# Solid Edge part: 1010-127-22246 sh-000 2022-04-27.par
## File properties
Author: lukasz.lemanski
Template: iso metric part.par
Last saved by: lukasz.lemanski
Revision: 1
Application: Solid Edge
Username: lukasz.lemanski
Gęstość: 0,000 kg/m^3
Dokładność: 0,990
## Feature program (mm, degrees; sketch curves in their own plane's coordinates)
body "unnamed Body 1"
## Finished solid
Body 1: solid body, 3347 faces, 8657 edges, 5599 vertices, 4 separate solids.
  Faces by surface: plane 2607, cylinder 338, spline 240, cone 78, torus 33, sphere 30, spun 21
  Edges by curve: line 7048, curve on surface 846, circle 433, ellipse 198, spline 114, intersection 18
Bounding box of the edges (mm; curved faces can reach further): 210.000 x 4.500 x 210.000, from (-105, -3.5, -105) to (105, 1, 105).
Cylindrical faces by radius (mm): R0.2 x117, R0.2002 x6, R0.2169 x9, R0.25 x36, R0.3 x6, R0.3373 x9, R0.4 x24, R0.4006 x6, R0.4008 x6, R0.525 x6, R0.6 x36, R1 x21, R1.0894 x6, R1.1 x42, R2.15 x4, R110 x4
Conical faces (half-angle, radius in mm at the cone's reference point): 0.5 deg R0.5056 x12, 0.5 deg R1.0082 x12, 1 deg R0.5511 x6, 10 deg R0.2132 x6, 10 deg R0.4132 x6, 18.4844 deg R1.0657 x12, 27.363 deg R0.6214 x6, 45 deg R0.575 x6, 45 deg R0.625 x12
Toroidal faces (ring radius, tube radius in mm): R0.1 r0.2 x3, R0.8 r0.2 x12, R0.8522 r0.3 x6, R0.9002 r0.2 x3, R0.9018 r0.2 x3, R1.3 r0.2 x6
Spherical faces by radius (mm): R0.2 x24, R0.6 x6
Planar faces by outward normal: +x 90, +y 34, +z 78, -x 90, -y 454, -z 105, oblique 1756
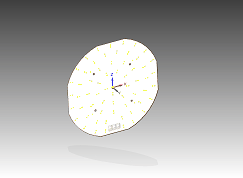
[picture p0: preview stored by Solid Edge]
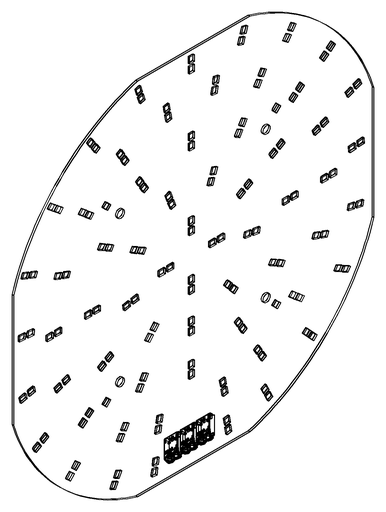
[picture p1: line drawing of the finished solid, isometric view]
